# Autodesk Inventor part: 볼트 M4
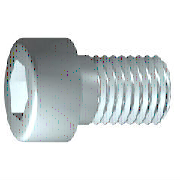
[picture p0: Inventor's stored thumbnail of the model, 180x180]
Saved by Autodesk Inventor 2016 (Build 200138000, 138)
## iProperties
IsCustomPart: 0
Created: 2018-09
Part Number: 볼트 M4
Material: 스테인리스강
Description: 6각머리 태핑 나사
Document SubType Name: Modeling
Standard: KS B 1003
Standards Organization: KS
Language: ko-KR
Size Designation: M 4 x 10
Categories: <MemberInstance><Categories><Category DisplayName="조임쇠" InternalName="e4da775c-781d-43d5-af7c-5136215cf5a6" Mnemonic="FSTN"><Category DisplayName="볼트" InternalN
Density: 8.08 g/cm^3
Appearance: 반광택
Mass: 2.09412 g
Surface Area: 3.0572 cm^2
Volume: 0.259174 cm^3
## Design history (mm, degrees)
sketch "스케치1"
  geometry: L1 (-1, 0)-(10, 0); L2 (10, 0)-(10, 2); L3 (10, 2)-(1.75, 2); L4 (1.75, 2)-(1.32, 2); L5 (1.32, 2)-(0, 2); L6 (0, 2)-(0, 3.5); L7 (0, 3.5)-(-4, 3.5); L8 (-4, 3.5)-(-4, 1.732); L9 (-4, 1.732)-(-2, 1.732); L10 (-2, 1.732)-(-1, 0); L11 (-6.8, 0)-(12.8, 0) reference; L12 (0, -0.7)-(0, 4.2) reference; L13 (1.75, 2)-(0, 2)
  constraints: 22 end point, 6 parallel, 2 collinear, 2 perpendicular, 1 horizontal, 1 point on line
  dimensions: "d1" = 8.25 distance from line of L3.end L2 (= GEL); "d2" = 0.42952 distance of L4.end L3.end (computed from GAL); "d3" = 4 distance between parallel lines of L8 L6 (= KOH); "d4" = 2 distance of L8.end L9.end (= INTI); "d5" = 60 deg angle of L10 L1; "d6" = 4 diameter of L3 L1 (= GD); "d7" = 4 diameter of L5 L1 (= BDM); "d8" = 3.4641 diameter of L9 L1 (= 1.1547 x SW); "d9" = 7 diameter of L7 L1 (= KOD); "d26" = 10 distance between parallel lines of L12 L2 (= NLG)
revolve "본체" sketch "스케치1" stored, may be unused: angle "d10" = 90 deg
sketch "스케치2"
  geometry: L1 (0, -4.9)-(0, 4.9) reference; L2 (-4.9, 0)-(4.9, 0) reference; L3 (1.732, 0)-(0.866, -1.5); L4 (0.866, -1.5)-(-0.866, -1.5); L5 (-0.866, -1.5)-(-1.732, 0); L6 (-1.732, 0)-(-0.866, 1.5); L7 (-0.866, 1.5)-(0.866, 1.5); L8 (0.866, 1.5)-(1.732, 0); 2 further points
  constraints: 12 end point, 1 coincident, 1 horizontal alignment, 1 point on line, 12 other
extrude "슬롯" join sketch "스케치2" stored distance "d11" = 10; taper "d12" = 0 deg
workplane "Work Plane1"
fillet "Fillet2" dims "d30" = 0.1 (= R)
body "Solid1"
fillet "모깎기1" dims "d17" = 0.4 (= RR)
feature "스레드" dims "d13" = 8.25 (= GEL), "d14" = 0
chamfer "모따기1" distance "d15" = 0.42941 (= -0.5 x SPD + 0.5 x GD); stored, may be unused: second distance "d16" = 0.42941 (= GUL), angle "d27" = 45 deg
other parameters: "GD" = 4 (= NND) [user parameter; used in 2 equation terms], "NLG" = 10 [user parameter; used in 1 equation term], "GEL" = 8.25 [user parameter; used in 2 equation terms], "KOD" = 7 [user parameter; used in 1 equation term], "KOH" = 4 [user parameter; used in 1 equation term], "INTI" = 2 [user parameter; used in 1 equation term], "GAL" = 0.42941 (= 0.61345 x PTC) [user parameter; used in 1 equation term], "GUL" = 0.42941 (= 0.61345 x PTC) [user parameter; used in 1 equation term], "BDM" = 4 (= NND) [user parameter; used in 1 equation term], "SW" = 3 [user parameter; used in 2 equation terms], "RR" = 0.4 [user parameter; used in 1 equation term], "SPD" = 3.14117 (= NND - 1.2269 x PTC) [user parameter; used in 1 equation term], "d19" = 0, "d28" = 0, "d29" = 0, "R" = 0.1 [user parameter; used in 1 equation term], "PHH" = 0.2 [user parameter], "GD1" = 3.14117 (= THREADDIA - 1.2269 x PTC) [user parameter], "THREADDIA" = 4 [user parameter; used in 1 equation term], "FAWI" = 45 deg [user parameter], "TPU" = 14.28571 (computed from PTC) [user parameter], "PTC" = 0.7 [user parameter; used in 5 equation terms], "NND" = 4 [user parameter; used in 3 equation terms], "TOA" = 30 deg [user parameter], "E0" = 3.465 (= 1.155 x SW) [user parameter]
